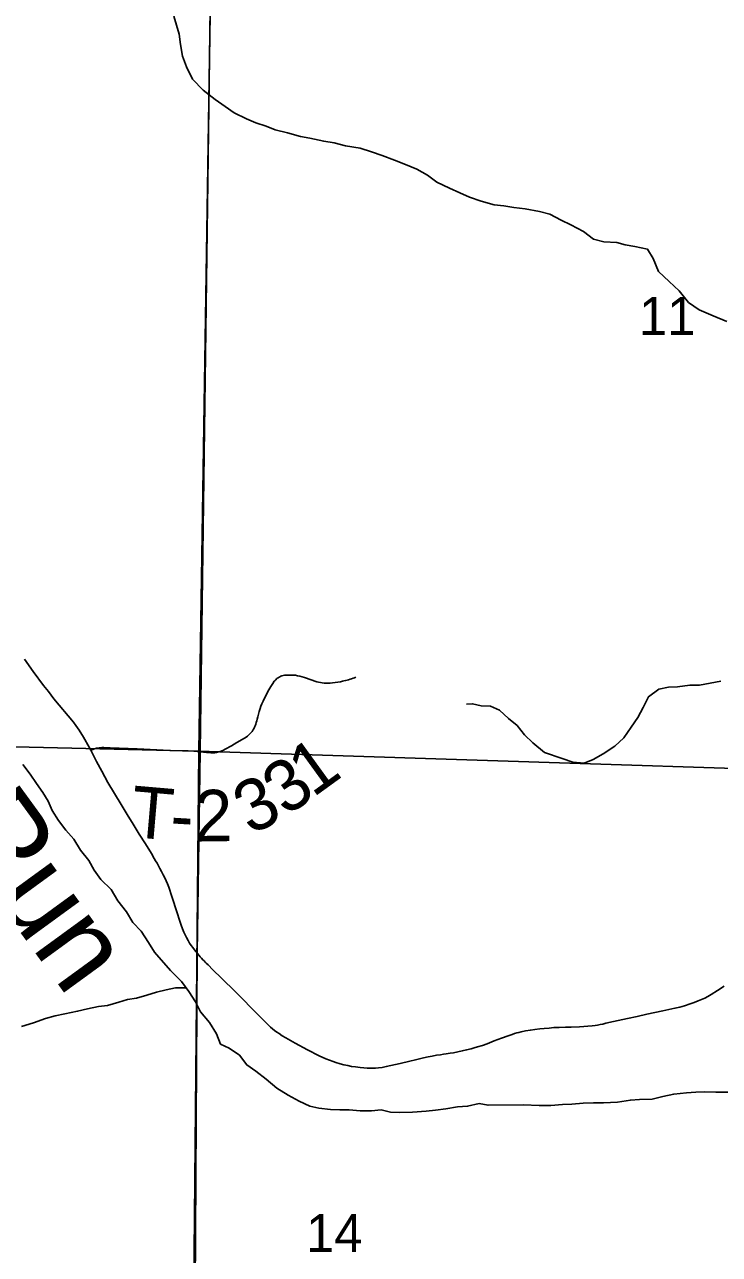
# Model space of a CAD drawing. Extents: x 0 to 34, y 0 to 22.
# Drawn here: x 2.589 to 3.356, y 19.687 to 21.043 of the extents above; entities that cross this region are included whole.
import ezdxf

# ---------------------------------------------------------------- set-up
doc = ezdxf.new("R2010")
doc.units = 0
for name, color, linetype in [('GM_X_Corporation', 7, 'Continuous'), ('GM_X_County_Road', 7, 'Continuous'), ('GM_X_Minor_River', 7, 'Continuous'), ('GM_X_Minor_River_Text', 7, 'Continuous'), ('GM_X_Section_Text', 7, 'Continuous'), ('GM_X_Township_Road', 7, 'Continuous'), ('GM_X_Township_Road_Text', 7, 'Continuous')]:
    doc.layers.add(name, color=color, linetype=linetype)

msp = doc.modelspace()

# ---------------------------------------------------------------- linework, layer by layer
at = {"layer": 'GM_X_Corporation'}
for points in [[(4.7823, 18.128), (4.0508, 18.1454), (3.7812, 18.1547), (3.7776, 18.3354), (3.7807, 18.4204), (3.7875, 18.9248), (3.7889, 19.1658), (3.7877, 19.187), (3.1142, 19.2057), (2.7749, 19.2162), (2.7798, 20.0198), (2.7831, 20.242), (2.7976, 21.3075), (2.7987, 21.3734), (1.6311, 21.3734), (1.6311, 16.1731), (2.3716, 16.1532), (2.3935, 16.1523), (3.7652, 16.1115), (4.1576, 16.1007)], [(8.4311, 21.3734), (2.7987, 21.3734), (2.7976, 21.3075), (2.7831, 20.242), (2.7798, 20.0198), (2.7749, 19.2162), (3.1142, 19.2057), (3.7877, 19.187), (3.7889, 19.1658), (3.7875, 18.9248), (3.7807, 18.4204), (3.7776, 18.3354), (3.7812, 18.1547), (4.0508, 18.1454), (4.7823, 18.128)]]:
    msp.add_lwpolyline(points, dxfattribs=at)
for points in [[(2.7974, 21.2696), (2.7815, 20.2421), (1.7685, 20.2662), (1.7888, 21.2952)], [(2.7974, 21.2696), (3.8139, 21.2086), (3.8046, 20.2092), (2.7815, 20.2421)], [(2.7815, 20.2421), (2.7721, 19.2162), (1.7459, 19.2387), (1.7685, 20.2662)], [(3.8046, 20.2092), (3.7879, 19.187), (2.7721, 19.2162), (2.7815, 20.2421)]]:
    msp.add_lwpolyline(points, close=True, dxfattribs=at)
at = {"layer": 'GM_X_County_Road'}
for points in [[(2.5894, 20.3435), (2.5991, 20.3299), (2.6102, 20.3146), (2.6157, 20.3078), (2.6217, 20.3), (2.6276, 20.2929), (2.6376, 20.2811), (2.6435, 20.274), (2.6461, 20.2706), (2.6496, 20.2655), (2.6546, 20.2577), (2.6561, 20.255), (2.6625, 20.2434)], [(2.6625, 20.2434), (2.6689, 20.2309), (2.6746, 20.2203), (2.6813, 20.2078), (2.6885, 20.1955), (2.6959, 20.1833), (2.7027, 20.1723), (2.7092, 20.1618), (2.7159, 20.1508), (2.7227, 20.14), (2.7293, 20.1294), (2.7325, 20.124), (2.734, 20.1214), (2.7356, 20.1188), (2.7372, 20.1159), (2.7388, 20.1128), (2.7406, 20.1095), (2.7425, 20.1059), (2.744, 20.1026), (2.7456, 20.0993), (2.747, 20.0959), (2.7484, 20.0924), (2.7496, 20.089), (2.7509, 20.0854), (2.7538, 20.0766), (2.7561, 20.0693), (2.7622, 20.0504), (2.7637, 20.0462), (2.765, 20.0428), (2.7665, 20.0398), (2.7681, 20.0366), (2.7698, 20.0334), (2.7715, 20.0307), (2.7733, 20.0278), (2.7749, 20.0256), (2.7767, 20.0233), (2.7783, 20.0213), (2.78, 20.0192)], [(2.78, 20.0192), (2.7817, 20.0173), (2.7832, 20.0155), (2.7846, 20.0139), (2.7862, 20.0123), (2.7874, 20.011), (2.7887, 20.0096), (2.7898, 20.0084), (2.7918, 20.0065), (2.7971, 20.0013), (2.8066, 19.992), (2.8221, 19.9767), (2.8479, 19.9507), (2.8558, 19.9427), (2.8608, 19.938), (2.863, 19.9362), (2.8652, 19.9344), (2.8675, 19.9326), (2.8702, 19.9308), (2.8737, 19.9285), (2.8776, 19.9261), (2.8878, 19.9202), (2.9015, 19.9128), (2.9143, 19.9064), (2.9216, 19.9031), (2.9257, 19.9014), (2.9298, 19.9), (2.9327, 19.899), (2.9374, 19.8976), (2.9416, 19.8965), (2.9461, 19.8955), (2.9501, 19.8947), (2.9545, 19.8941), (2.9595, 19.8935), (2.9636, 19.8931), (2.9671, 19.8928), (2.9701, 19.8927), (2.9729, 19.8926), (2.9763, 19.8927), (2.9798, 19.8931), (2.9839, 19.8936), (2.9884, 19.8945), (3.0036, 19.8979), (3.0144, 19.9006), (3.0205, 19.902), (3.0293, 19.9041), (3.0344, 19.9052), (3.0391, 19.9061), (3.0439, 19.9069), (3.0483, 19.9076), (3.0514, 19.908), (3.0544, 19.9085), (3.0587, 19.9091), (3.0624, 19.9097), (3.0671, 19.9107), (3.0721, 19.9117), (3.0769, 19.9128), (3.0818, 19.914), (3.0853, 19.915), (3.089, 19.9161), (3.0943, 19.9178), (3.0996, 19.9197), (3.1075, 19.9227), (3.1153, 19.9257), (3.1229, 19.9285), (3.1273, 19.93), (3.1297, 19.9309), (3.1322, 19.9316), (3.1346, 19.9322), (3.1371, 19.9328), (3.142, 19.9338), (3.1473, 19.9347), (3.1522, 19.9354), (3.1576, 19.9361), (3.1626, 19.9366), (3.1679, 19.937), (3.1733, 19.9374), (3.1791, 19.9376), (3.1859, 19.9378), (3.1921, 19.938), (3.2014, 19.9384), (3.2061, 19.9386), (3.2108, 19.939), (3.2153, 19.9395), (3.2187, 19.9399), (3.2214, 19.9403), (3.2241, 19.9408), (3.2271, 19.9414), (3.2306, 19.9422), (3.2389, 19.944), (3.2543, 19.9474), (3.2651, 19.9497), (3.2756, 19.9521), (3.2933, 19.9558), (3.3067, 19.9587), (3.3122, 19.96), (3.3174, 19.9614), (3.3235, 19.9635), (3.328, 19.9651), (3.3322, 19.9668), (3.336, 19.9683), (3.3395, 19.97), (3.343, 19.9719), (3.3468, 19.974), (3.3538, 19.9782), (3.3609, 19.9832)]]:
    msp.add_lwpolyline(points, dxfattribs=at)
at = {"layer": 'GM_X_Minor_River'}
for points in [[(3.3638, 20.7157), (3.349, 20.722), (3.3335, 20.7287), (3.3217, 20.7369), (3.3113, 20.7497), (3.3003, 20.7598), (3.2885, 20.771), (3.2827, 20.7854), (3.2765, 20.7955), (3.2625, 20.7984), (3.2519, 20.8002), (3.2425, 20.8031), (3.2281, 20.8037), (3.2167, 20.8066), (3.2057, 20.8152), (3.192, 20.8223), (3.1814, 20.8275), (3.1689, 20.8342), (3.1575, 20.8371), (3.1416, 20.8399), (3.1291, 20.8417), (3.1181, 20.8435), (3.1075, 20.8445), (3.0931, 20.8485), (3.0802, 20.8529), (3.0696, 20.8578), (3.0582, 20.8629), (3.0442, 20.8696), (3.0339, 20.8771), (3.0221, 20.8838), (3.0096, 20.889), (2.9975, 20.8938), (2.9838, 20.8989), (2.9721, 20.903), (2.9596, 20.907), (2.9433, 20.9095), (2.9308, 20.9128), (2.9194, 20.9145), (2.9039, 20.9178), (2.8937, 20.9199), (2.8793, 20.924), (2.866, 20.9272), (2.8558, 20.9313), (2.8444, 20.935), (2.8341, 20.9394), (2.8205, 20.9457), (2.8106, 20.9528), (2.7996, 20.9606), (2.7866, 20.9707), (2.7748, 20.9831), (2.7679, 20.9967), (2.7636, 21.0084), (2.7616, 21.0212), (2.76, 21.0326), (2.7542, 21.0526)], [(3.3574, 20.3194), (3.3337, 20.315), (3.3231, 20.3148), (3.3095, 20.3132), (3.2997, 20.3127), (3.2891, 20.3107), (3.2774, 20.3022), (3.2715, 20.2904), (3.2659, 20.2794), (3.2585, 20.2687), (3.2502, 20.2569)], [(3.2502, 20.2569), (3.2405, 20.2477), (3.2277, 20.2392), (3.2164, 20.233), (3.2066, 20.2291), (3.1941, 20.2301), (3.1824, 20.2342), (3.1627, 20.2408), (3.1501, 20.2513), (3.1406, 20.2603), (3.1326, 20.2704), (3.123, 20.2783), (3.1131, 20.2873), (3.1033, 20.2917), (3.0931, 20.292), (3.0836, 20.2945), (3.0768, 20.2941)], [(3.3663, 19.8664), (3.3519, 19.8662), (3.3394, 19.8668), (3.3296, 19.8663), (3.3194, 19.8655), (3.3054, 19.8642), (3.2934, 19.8614), (3.2817, 19.8586), (3.2677, 19.8581), (3.2575, 19.8576), (3.2432, 19.8552), (3.228, 19.8547), (3.2167, 19.8546), (3.2054, 19.8541), (3.1929, 19.8532), (3.1827, 19.8527), (3.1698, 19.8514), (3.157, 19.8517), (3.1396, 19.8522), (3.1007, 19.8518), (3.0908, 19.8536), (3.078, 19.8508), (3.067, 19.85), (3.0542, 19.8479), (3.0425, 19.8463), (3.0323, 19.8454), (3.0172, 19.8441), (3.0028, 19.844), (2.993, 19.8443), (2.9828, 19.8468), (2.9722, 19.8456), (2.9597, 19.8458), (2.9476, 19.8468), (2.937, 19.8467), (2.9268, 19.847), (2.914, 19.8487), (2.9041, 19.8509), (2.8923, 19.8565), (2.8802, 19.8628), (2.8676, 19.8706), (2.8558, 19.8807), (2.8444, 19.8893), (2.8345, 19.8964), (2.8265, 19.9069), (2.8151, 19.9148), (2.8056, 19.9192), (2.8013, 19.9305), (2.7933, 19.9429), (2.7834, 19.955), (2.778, 19.9659), (2.7707, 19.9772), (2.7627, 19.9881), (2.7505, 20.0005), (2.7329, 20.0207), (2.726, 20.0313), (2.718, 20.0437), (2.7088, 20.0534), (2.7019, 20.0651), (2.6923, 20.0771), (2.685, 20.0896), (2.6736, 20.1008), (2.6663, 20.111), (2.6602, 20.1215), (2.651, 20.1332), (2.6437, 20.1452), (2.635, 20.155), (2.6269, 20.1659), (2.62, 20.1768), (2.6154, 20.187), (2.6096, 20.1967), (2.6028, 20.2065), (2.5955, 20.2167), (2.5874, 20.2276)], [(2.7676, 19.9814), (2.7559, 19.9812), (2.7457, 19.9792), (2.7348, 19.9764), (2.7242, 19.9733), (2.7129, 19.9698), (2.7031, 19.9685), (2.6933, 19.9654), (2.6809, 19.9618), (2.671, 19.9606), (2.659, 19.9582), (2.648, 19.9554), (2.6337, 19.9526), (2.6231, 19.9503), (2.6126, 19.9475), (2.5994, 19.9428), (2.5862, 19.9385)]]:
    msp.add_lwpolyline(points, dxfattribs=at)
at = {"layer": 'GM_X_Township_Road'}
for points in [[(2.7833, 20.2414), (2.7901, 20.2407), (2.795, 20.2403), (2.7972, 20.2403), (2.7993, 20.2405), (2.8012, 20.2408), (2.8032, 20.2413), (2.805, 20.2418), (2.8069, 20.2425), (2.8088, 20.2433), (2.8107, 20.2443), (2.8177, 20.2481), (2.8235, 20.2516), (2.8319, 20.2566), (2.8337, 20.2578), (2.8353, 20.2589), (2.8369, 20.2602), (2.8382, 20.2615), (2.8393, 20.2626), (2.8403, 20.2639), (2.8413, 20.2653), (2.8423, 20.2669), (2.8431, 20.2685), (2.8439, 20.2702), (2.8445, 20.272), (2.845, 20.2737), (2.8456, 20.2756), (2.846, 20.2773), (2.8467, 20.2802), (2.8482, 20.286), (2.8492, 20.2892), (2.8501, 20.2918), (2.8512, 20.2944), (2.8526, 20.2974), (2.8541, 20.3006), (2.8589, 20.3098), (2.8611, 20.3136), (2.8632, 20.3169), (2.8649, 20.3192), (2.8657, 20.3202), (2.8665, 20.321), (2.8673, 20.3218), (2.8682, 20.3225), (2.8691, 20.3232), (2.8701, 20.3238), (2.8709, 20.3243), (2.872, 20.3248), (2.8732, 20.3252), (2.8747, 20.3255), (2.8763, 20.3258), (2.8777, 20.3259), (2.8793, 20.3261), (2.8811, 20.3261), (2.8829, 20.3261), (2.8855, 20.326), (2.8881, 20.3258), (2.8906, 20.3254), (2.8931, 20.3248), (2.8982, 20.3233), (2.9116, 20.3188), (2.9137, 20.3182), (2.916, 20.3178), (2.9178, 20.3175), (2.9197, 20.3173), (2.9218, 20.3172), (2.9241, 20.3172), (2.9265, 20.3173), (2.9291, 20.3175), (2.932, 20.3179), (2.9348, 20.3183), (2.9377, 20.3187), (2.9399, 20.3192), (2.9417, 20.3196), (2.9435, 20.32), (2.9452, 20.3204), (2.9468, 20.3209), (2.9486, 20.3214), (2.9501, 20.322), (2.9517, 20.3225), (2.9533, 20.3232), (2.9548, 20.3238)], [(2.6625, 20.2434), (2.6687, 20.2455), (2.6719, 20.246), (2.6745, 20.2461), (2.6769, 20.2461), (2.6837, 20.246), (2.7135, 20.2447), (2.7497, 20.2429), (2.7636, 20.2425), (2.7698, 20.2424), (2.7762, 20.2421), (2.7833, 20.2414)]]:
    msp.add_lwpolyline(points, dxfattribs=at)

# ---------------------------------------------------------------- texts
at = {"layer": 'GM_X_Minor_River_Text'}
msp.add_text('Crane Run', height=0.09469, rotation=306.0663, dxfattribs=at).set_placement((2.2773, 20.4644))
at = {"layer": 'GM_X_Section_Text'}
for s, p in [('11', (3.267, 20.701)), ('14', (2.8999, 19.69))]:
    msp.add_text(s, height=0.04186, rotation=0, dxfattribs=at).set_placement(p)
at = {"layer": 'GM_X_Township_Road_Text'}
for s, rotation, p in [('1', 35.9276, (2.9074, 20.1904)), ('3', 35.1911, (2.8781, 20.1697)), ('T', 355.0677, (2.7051, 20.1477)), ('2', 0.7608, (2.7768, 20.1425)), ('3', 26.2489, (2.8384, 20.1493)), ('-', 356.6315, (2.7491, 20.1439))]:
    msp.add_text(s, height=0.0568, rotation=rotation, dxfattribs=at).set_placement(p)

doc.saveas('drawing.dxf')
